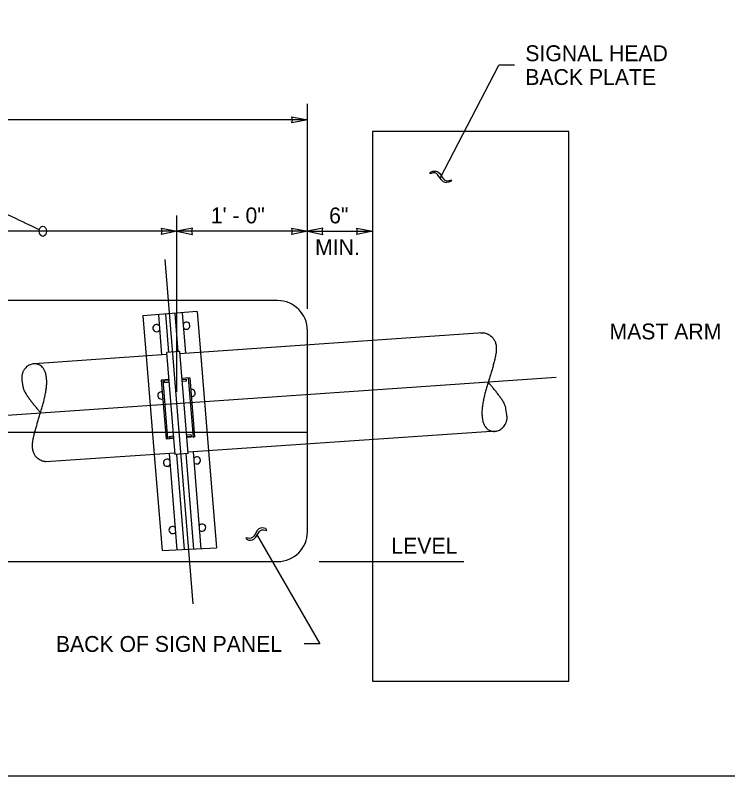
# Model space of a CAD drawing. Extents: x 99862 to 104211, y 98939 to 105076.
# Drawn here: x 101151 to 101870, y 100000 to 100767 of the extents above; entities that cross this region are included whole.
import ezdxf

# ---------------------------------------------------------------- set-up
doc = ezdxf.new("R2010")
doc.units = 0
for name, color, linetype in [('Level 1', 7, 'Continuous'), ('Level 15', 7, 'Continuous'), ('Level 16', 7, 'Continuous'), ('Level 2', 7, 'Continuous'), ('Level 20', 7, 'Continuous'), ('Level 21', 7, 'Continuous'), ('Level 3', 7, 'Continuous'), ('Level 6', 7, 'Continuous'), ('Level 7', 7, 'Continuous')]:
    doc.layers.add(name, color=color, linetype=linetype)

msp = doc.modelspace()

# ---------------------------------------------------------------- linework, layer by layer
at = {"layer": 'Level 1'}
for p, q in [((101415.69, 100478.94), (100423.73, 100478.94)), ((101445.69, 100434.29), (101445.69, 100448.94)), ((101445.69, 100245.69), (101445.69, 100334.23)), ((100423.73, 100215.69), (101415.69, 100215.69))]:
    msp.add_line(p, q, dxfattribs=at)
msp.add_lwpolyline([(99862, 99999.5), (103151, 99999.5), (103151, 102075.5), (99862, 102075.5)], close=True, dxfattribs=at)
msp.add_lwpolyline([(101445.69, 100334.23), (101445.69, 100434.29)], dxfattribs=at)
for centre, start, end in [((101415.69, 100448.94), 0, 90), ((101415.69, 100245.69), 270, 360)]:
    msp.add_arc(centre, 30, start, end, dxfattribs=at)
at = {"layer": 'Level 15'}
for p, q in [((101579.73, 100602.52), (101638.8, 100716.59)), ((101654.8, 100716.59), (101638.8, 100716.59)), ((101445.69, 100470.71), (101445.69, 100677.51)), ((101445.69, 100661.51), (100393.73, 100661.51)), ((101569.37, 100606.87), (101570.42, 100608.7)), ((101572.94, 100607.8), (101569.37, 100606.87)), ((101570.42, 100608.7), (101572.44, 100609.45)), ((101572.44, 100609.45), (101574.2, 100609.72)), ((101574.59, 100607.75), (101572.94, 100607.8)), ((101574.2, 100609.72), (101575.8, 100609.54)), ((101575.93, 100607.27), (101574.59, 100607.75)), ((101575.8, 100609.54), (101577.33, 100608.9)), ((101577.33, 100608.9), (101579.26, 100607.35)), ((101577.09, 100606.32), (101575.93, 100607.27)), ((101578.47, 100604.33), (101577.09, 100606.32)), ((101580.99, 100600.71), (101578.47, 100604.33)), ((101579.26, 100607.35), (101581.53, 100603.95)), ((101583.08, 100598.96), (101580.99, 100600.71)), ((101581.53, 100603.95), (101582.99, 100601.86)), ((101582.99, 100601.86), (101584.45, 100600.61)), ((101584.45, 100600.61), (101585.68, 100600.11)), ((101585.68, 100600.11), (101587.04, 100599.96)), ((101587.04, 100599.96), (101588.75, 100600.23)), ((101588.75, 100600.23), (101591.06, 100600.97)), ((101591.06, 100600.97), (101590, 100599.14)), ((101584.7, 100598.28), (101583.08, 100598.96)), ((101586.4, 100598.09), (101584.7, 100598.28)), ((101588.17, 100598.38), (101586.4, 100598.09)), ((101590, 100599.14), (101588.17, 100598.38)), ((101314.07, 100424.93), (101314.07, 100564.94)), ((101314.07, 100548.94), (101050.57, 100548.94)), ((101445.69, 100548.94), (101314.07, 100548.94)), ((101445.69, 100548.94), (101511.3, 100548.94)), ((101330.59, 100173.17), (101302.15, 100520.48)), ((101314.07, 100386.86), (101314.07, 100424.93)), ((101696.61, 100401.42), (100196.26, 100297.76)), ((101445.69, 100345.88), (100393.73, 100345.88)), ((101395, 100246.91), (101392.97, 100243.36)), ((101396.81, 100248.58), (101395, 100246.91)), ((101398.29, 100249.34), (101396.81, 100248.58)), ((101397.23, 100246.03), (101398.32, 100247.06)), ((101399.88, 100249.62), (101398.29, 100249.34)), ((101398.32, 100247.06), (101399.63, 100247.63)), ((101399.63, 100247.63), (101401.26, 100247.8)), ((101401.66, 100249.48), (101399.88, 100249.62)), ((101401.26, 100247.8), (101404.9, 100247.12)), ((101403.72, 100248.87), (101401.66, 100249.48)), ((101404.9, 100247.12), (101403.72, 100248.87)), ((101386.02, 100239.15), (101383.66, 100239.73)), ((101383.66, 100239.73), (101384.84, 100237.98)), ((101387.75, 100239), (101386.02, 100239.15)), ((101389.09, 100239.24), (101387.75, 100239)), ((101390.29, 100239.82), (101389.09, 100239.24)), ((101391.65, 100241.18), (101390.29, 100239.82)), ((101392.97, 100243.36), (101391.65, 100241.18)), ((101391.77, 100238.27), (101393.72, 100240.16)), ((101393.72, 100240.16), (101395.99, 100243.95)), ((101394.32, 100243.43), (101458.35, 100132.53)), ((101395.99, 100243.95), (101397.23, 100246.03)), ((101384.84, 100237.98), (101386.73, 100237.34)), ((101386.73, 100237.34), (101388.51, 100237.17)), ((101388.51, 100237.17), (101390.19, 100237.49)), ((101390.19, 100237.49), (101391.77, 100238.27)), ((101457.46, 100215.69), (101603.63, 100215.69)), ((101458.35, 100132.53), (101442.35, 100132.53))]:
    msp.add_line(p, q, dxfattribs=at)
for points in [[(101445.69, 100661.51), (101429.97, 100658.43), (101430.69, 100661.51), (101429.97, 100664.59)], [(101314.07, 100548.94), (101298.35, 100545.85), (101299.08, 100548.94), (101298.35, 100552.02)], [(101314.07, 100548.94), (101329.8, 100545.85), (101329.07, 100548.94), (101329.8, 100552.02)], [(101445.69, 100548.94), (101429.97, 100545.85), (101430.69, 100548.94), (101429.97, 100552.02)], [(101445.69, 100548.94), (101461.42, 100545.85), (101460.69, 100548.94), (101461.42, 100552.02)], [(101511.3, 100548.94), (101495.58, 100545.85), (101496.31, 100548.94), (101495.58, 100552.02)]]:
    msp.add_lwpolyline(points, close=True, dxfattribs=at)
msp.add_ellipse((101178.75, 100548.94), major_axis=(0, 5.11), ratio=0.71273, dxfattribs=at)
msp.add_open_spline([(100771.84, 100615.88), (101038.06, 100615.88), (101146.32, 100564.37), (101171.28, 100552.49), (101175.31, 100550.58)], degree=3, dxfattribs=at)
at = {"layer": 'Level 16'}
for p, q in [((101622.77, 100446.53), (101317.1, 100425.41)), ((101303.82, 100424.49), (101170.23, 100415.26)), ((101636.23, 100347.22), (101325.23, 100326.1)), ((101311.95, 100325.2), (101181.7, 100316.41))]:
    msp.add_line(p, q, dxfattribs=at)
for points in [[(101157.67, 100398.64), (101158.66, 100392.26)], [(101647, 100363.74), (101646.06, 100369.76)]]:
    msp.add_lwpolyline(points, dxfattribs=at)
for points in [[(101620.42, 100446.37), (101620.68, 100446.41), (101621.66, 100446.56), (101623.32, 100446.55), (101625.37, 100446.2), (101627.47, 100445.47), (101629.56, 100444.4), (101631.61, 100442.79), (101633.54, 100440.63), (101635.18, 100437.76), (101635.88, 100435.35), (101636.11, 100433.92)], [(101636.11, 100433.92), (101636.32, 100432.56), (101636.44, 100429.65), (101635.94, 100425.13), (101635.04, 100420.67), (101633.93, 100416.25), (101632.7, 100411.8), (101631.38, 100407.42), (101630.06, 100403.09), (101628.69, 100398.69), (101627.32, 100394.23), (101626.02, 100389.78), (101624.8, 100385.2), (101623.72, 100380.59), (101622.8, 100375.86), (101622.07, 100371.1), (101621.74, 100366.4), (101621.92, 100361.84), (101622.55, 100357.75), (101623.67, 100354.41), (101625.15, 100351.71), (101626.92, 100349.73), (101628.79, 100348.36), (101630.72, 100347.46), (101632.72, 100347.04), (101634.72, 100346.95), (101636.67, 100347.26), (101638.63, 100347.89), (101640.54, 100348.85), (101642.26, 100350.18), (101643.93, 100351.84), (101645.39, 100353.99), (101646.57, 100356.63), (101647.27, 100359.86), (101647.21, 100362.38), (101647, 100363.74)], [(101168.49, 100328.93), (101168.28, 100330.28), (101168.16, 100333.17), (101168.65, 100337.66), (101169.55, 100342.09), (101170.65, 100346.48), (101171.88, 100350.9), (101173.18, 100355.26), (101174.49, 100359.55), (101175.86, 100363.92), (101177.22, 100368.35), (101178.51, 100372.78), (101179.72, 100377.32), (101180.79, 100381.91), (101181.71, 100386.6), (101182.43, 100391.33), (101182.76, 100396), (101182.58, 100400.53), (101181.95, 100404.59), (101180.84, 100407.91), (101179.37, 100410.59), (101177.61, 100412.56), (101175.75, 100413.92), (101173.83, 100414.81), (101171.86, 100415.23), (101169.86, 100415.31), (101167.93, 100415.01), (101165.98, 100414.38), (101164.09, 100413.43), (101162.38, 100412.11), (101160.72, 100410.46), (101159.27, 100408.33), (101158.09, 100405.7), (101157.4, 100402.49), (101157.46, 100399.99), (101157.67, 100398.64)], [(101646, 100370.16), (101645.82, 100371.33), (101645.13, 100373.61), (101643.35, 100376.99), (101641.32, 100380.19), (101639.05, 100383.3), (101636.64, 100386.38), (101634.25, 100389.39), (101631.72, 100392.39), (101629.68, 100394.86), (101628.45, 100396.33), (101628.12, 100396.75)], [(101158.66, 100392.26), (101158.84, 100391.1), (101159.52, 100388.83), (101161.3, 100385.48), (101163.31, 100382.3), (101165.57, 100379.21), (101167.96, 100376.15), (101170.33, 100373.16), (101172.84, 100370.18), (101174.87, 100367.73), (101176.09, 100366.27), (101176.42, 100365.85)], [(101181.7, 100316.41), (101181.53, 100316.41), (101180.68, 100316.47), (101179.16, 100316.73), (101177.06, 100317.46), (101174.99, 100318.52), (101172.96, 100320.12), (101171.04, 100322.26), (101169.41, 100325.11), (101168.71, 100327.51), (101168.49, 100328.93)]]:
    msp.add_open_spline(points, degree=3, dxfattribs=at)
at = {"layer": 'Level 2'}
for p, q in [((101334.4, 100467.94), (101279.78, 100463.46)), ((101279.78, 100463.46), (101283.09, 100423.06)), ((101295.3, 100464.73), (101298.5, 100424.12)), ((101302.59, 100465.33), (101305.64, 100426.72)), ((101312.02, 100466.1), (101315.06, 100427.49)), ((101319.33, 100466.7), (101322.57, 100425.79)), ((101334.4, 100467.94), (101337.77, 100426.84)), ((101337.77, 100426.84), (101337.78, 100426.69)), ((101337.78, 100426.69), (101345.9, 100327.54)), ((101283.09, 100423.06), (101283.13, 100422.64)), ((101283.09, 100423.06), (101291.23, 100323.66)), ((101291.23, 100323.66), (101291.25, 100323.45)), ((101291.25, 100323.45), (101299.17, 100226.69)), ((101306.34, 100324.83), (101314.04, 100227.41)), ((101313.76, 100323.84), (101321.35, 100227.77)), ((101323.19, 100324.61), (101330.8, 100228.23)), ((101330.41, 100326.44), (101338.14, 100228.59)), ((101345.9, 100327.54), (101345.92, 100327.3)), ((101345.92, 100327.3), (101353.94, 100229.36)), ((101299.17, 100226.69), (101353.94, 100229.36))]:
    msp.add_line(p, q, dxfattribs=at)
at = {"layer": 'Level 21'}
msp.add_line((101511.3, 100438.83), (101511.3, 100338.66), dxfattribs=at)
for points in [[(101511.3, 100338.66), (101511.3, 100095.11), (101709.66, 100095.11), (101709.66, 100649.62), (101511.3, 100649.62)], [(101511.3, 100649.62), (101511.3, 100438.83)]]:
    msp.add_lwpolyline(points, dxfattribs=at)
at = {"layer": 'Level 3'}
for p, q in [((101327, 100401.13), (101319.14, 100400.49)), ((101325.46, 100401.01), (101330.34, 100341.32)), ((101327, 100401.13), (101331.89, 100341.44)), ((101305.88, 100399.4), (101298.26, 100398.78)), ((101298.26, 100398.78), (101303.15, 100339.09)), ((101299.81, 100398.9), (101304.7, 100339.22)), ((101301.47, 100397.93), (101305.97, 100398.3)), ((101301.59, 100396.38), (101301.47, 100397.93)), ((101301.59, 100396.38), (101306.09, 100396.75)), ((101319.23, 100399.38), (101323.57, 100399.74)), ((101319.36, 100397.84), (101323.7, 100398.19)), ((101323.7, 100398.19), (101323.57, 100399.74)), ((101310.76, 100339.71), (101303.15, 100339.09)), ((101306.05, 100342), (101310.55, 100342.37)), ((101306.05, 100342), (101306.17, 100340.45)), ((101306.17, 100340.45), (101310.67, 100340.82)), ((101323.81, 100343.45), (101328.15, 100343.81)), ((101323.94, 100341.91), (101328.28, 100342.26)), ((101331.89, 100341.44), (101324.03, 100340.8)), ((101328.15, 100343.81), (101328.28, 100342.26)), ((101330.34, 100341.32), (101331.89, 100341.44))]:
    msp.add_line(p, q, dxfattribs=at)
at = {"layer": 'Level 6'}
for centre, start, end in [((101293.44, 100451.21), 41.47093, 327.55941), ((101323.56, 100453.7), 213.74543, 155.28491), ((101298.39, 100383.3), 76.55992, 292.80399), ((101328.86, 100385.76), 265.3535, 104.01041), ((101304.04, 100315.39), 38.28174, 330.7486), ((101334.15, 100317.82), 217.76903, 151.26131), ((101309.7, 100247.48), 45.7288, 319.25452), ((101339.45, 100249.88), 219.62594, 152.43417)]:
    msp.add_arc(centre, 3.65, start, end, dxfattribs=at)
at = {"layer": 'Level 7'}
for p, q in [((101316.92, 100427.62), (101303.65, 100426.53)), ((101303.65, 100426.53), (101312.08, 100323.68)), ((101325.34, 100324.77), (101316.92, 100427.62)), ((101325.34, 100324.77), (101312.08, 100323.68))]:
    msp.add_line(p, q, dxfattribs=at)

# ---------------------------------------------------------------- texts
at = {"layer": 'Level 20'}
for s, p in [('SIGNAL HEAD', (101665.59, 100720.59)), ('BACK PLATE', (101665.59, 100696.59)), ('1\' - 0"', (101348.23, 100556.94)), ('6"', (101467.63, 100556.94)), ('MIN.', (101453.45, 100524.94)), ('MAST ARM', (101750.54, 100439.87)), ('LEVEL', (101530.44, 100223.69)), ('BACK OF SIGN PANEL', (101191.89, 100124.53))]:
    msp.add_text(s, height=16, dxfattribs=at).set_placement(p)

doc.saveas('drawing.dxf')
